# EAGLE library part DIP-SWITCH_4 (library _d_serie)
DIP-Switch 4-fach
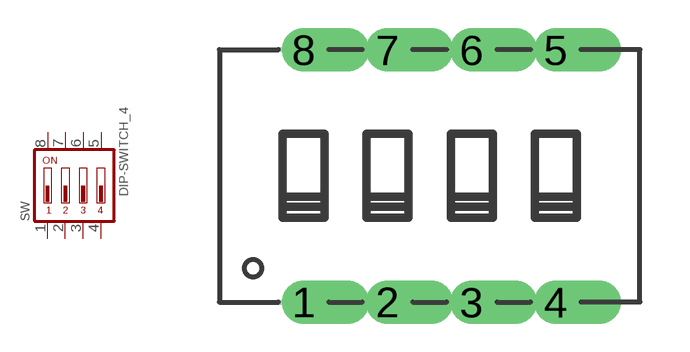
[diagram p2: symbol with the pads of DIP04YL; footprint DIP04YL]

Designator prefix SW

## DIP-SWITCH_4  [DIP04YL]
1  1  pas
2  2  pas
3  3  pas
4  4  pas
5  5  pas
6  6  pas
7  7  pas
8  8  pas

## Footprint DIP04YL (pad centres in mm)
DIP-Switch 4-fach
drill 0.813 offset: 1 -3.81,-3.81; 2 -1.27,-3.81; 3 1.27,-3.81; 4 3.81,-3.81; 5 3.81,3.81; 6 1.27,3.81; 7 -1.27,3.81; 8 -3.81,3.81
